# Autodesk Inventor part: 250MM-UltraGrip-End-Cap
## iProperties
Created: 2012-04
Part Number: 250MM-UltraGrip-End-Cap
Document SubType Name: Modeling
Designer: D Cole
Density: 1 g/cm^3
Author: D Cole
